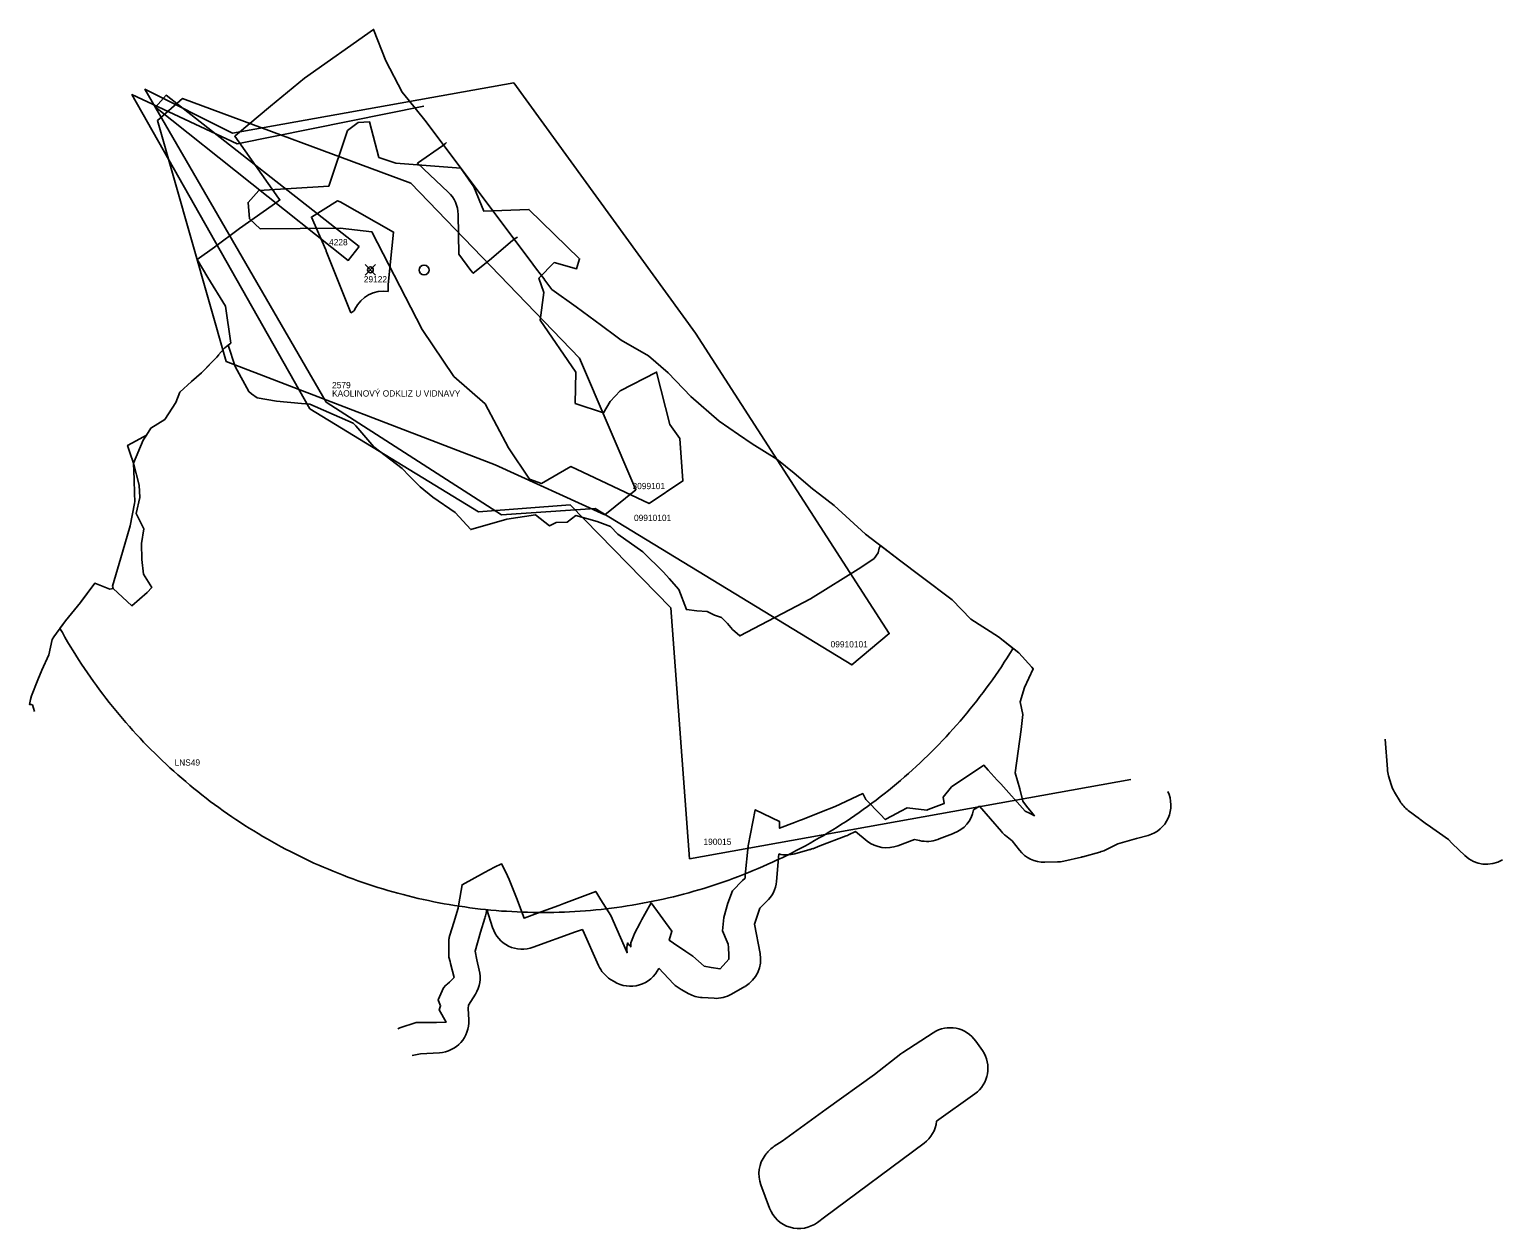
# Model space of a CAD drawing. Extents: x -546762 to -536351, y -1046851 to -1035695.
# Drawn here: x -543675 to -541320, y -1037611 to -1035695 of the extents above; entities that cross this region are included whole.
import ezdxf

# ---------------------------------------------------------------- set-up
doc = ezdxf.new("R2010")
doc.units = 0
for name, color, linetype in [('Vrstva 16', 7, 'Continuous'), ('Vrstva 23', 7, 'Continuous'), ('Vrstva 25', 7, 'Continuous'), ('Vrstva 40', 7, 'Continuous'), ('Vrstva 41', 7, 'Continuous'), ('Vrstva 46', 7, 'Continuous'), ('Vrstva 48', 7, 'Continuous'), ('Vrstva 50', 7, 'Continuous'), ('Vrstva 51', 7, 'Continuous'), ('Vrstva 53', 7, 'Continuous')]:
    doc.layers.add(name, color=color, linetype=linetype)

msp = doc.modelspace()

# ---------------------------------------------------------------- linework, layer by layer
at = {"layer": 'Vrstva 16'}
msp.add_circle((-543043.6, -1036078.9), 7.89, dxfattribs=at)
at = {"layer": 'Vrstva 23'}
for points in [[(-543005.1, -1035954.5), (-543054.3, -1035908.2), (-543014.2, -1035880.6)], [(-543200.8, -1036046.9), (-543223.9, -1035994.4), (-543182.2, -1035968.6), (-543177.6, -1035970.1), (-543092.4, -1036018.3), (-543101, -1036101.8)], [(-542902.1, -1036031.7), (-542939, -1036063.2), (-542965.2, -1036084.2), (-542968.8, -1036079.7), (-542988.1, -1036053.7), (-542989.3, -1035990)], [(-543160.9, -1036147.4), (-543200.1, -1036048.7)], [(-543154.3, -1036141.6), (-543155.4, -1036144), (-543155.9, -1036144.3)], [(-541507, -1036828.4), (-541503.7, -1036876.6)], [(-541501.8, -1036887.1), (-541497.7, -1036901.2)], [(-541492.5, -1036913.1), (-541483.5, -1036928.2)], [(-542165.4, -1036941.7), (-542155.8, -1036935.8), (-542120.8, -1036976.3)], [(-541470.5, -1036942.5), (-541452.2, -1036956.1)], [(-541452, -1036956.2), (-541441, -1036964.3)], [(-541440.3, -1036964.8), (-541406, -1036989.2), (-541400.6, -1036994.7)], [(-542422.4, -1037003.6), (-542410.8, -1036999.1), (-542368.7, -1036983)], [(-542365.4, -1036981.6), (-542354.2, -1036976.3), (-542335.1, -1036991.4)], [(-542286.2, -1036998.9), (-542259.8, -1036988.8), (-542251.6, -1036990.7)], [(-542222.5, -1036988.8), (-542220, -1036987.8), (-542220, -1036987.8), (-542198.9, -1036979.8)], [(-542198.8, -1036979.8), (-542196.7, -1036979)], [(-542114.1, -1036982.8), (-542103.6, -1036991.2), (-542092.1, -1037006)], [(-541955, -1037005.8), (-541934.4, -1036995.9), (-541904.9, -1036987.6), (-541886.4, -1036982.4)], [(-542480.5, -1037055.9), (-542476.7, -1037012)], [(-542451, -1037011.7), (-542427, -1037005.1)], [(-542021.1, -1037023.6), (-541992.6, -1037017)], [(-541990.7, -1037016.5), (-541963.4, -1037009)], [(-541399.4, -1036995.9), (-541379.7, -1037014.7)], [(-542051.5, -1037025.3), (-542031.3, -1037024.8)], [(-542506.5, -1037171.1), (-542515.5, -1037124.1), (-542507.2, -1037098.4), (-542496.1, -1037088.1)], [(-542944.6, -1037106.9), (-542943.6, -1037100.8), (-542934.2, -1037129.8)], [(-542955.5, -1037197.6), (-542959.5, -1037181), (-542962.2, -1037167.2), (-542953.6, -1037136.9), (-542946.4, -1037114.5)], [(-542869.3, -1037161.2), (-542801.7, -1037136.3), (-542790.5, -1037132.8), (-542789.7, -1037134), (-542764.9, -1037190.1)], [(-542668.4, -1037194.8), (-542644.8, -1037219.5)], [(-542745.5, -1037212.4), (-542739.9, -1037215.9)], [(-542632.8, -1037228.7), (-542620.4, -1037235.5)], [(-542552.1, -1037236.1), (-542530.7, -1037223.8)], [(-542972.4, -1037277.1), (-542973.4, -1037258.9), (-542972.7, -1037253.5), (-542961.7, -1037236)], [(-542599.3, -1037241.6), (-542580.1, -1037242.7)], [(-542230.1, -1037297.9), (-542278.2, -1037329.4)], [(-542151.2, -1037326.2), (-542161.6, -1037311.2)], [(-543062.6, -1037334.3), (-543049.6, -1037331.6), (-543019.3, -1037329.8)], [(-542281.5, -1037331.7), (-542323.9, -1037364.6), (-542400.7, -1037419.6)], [(-542224.4, -1037439.2), (-542163.2, -1037395.4)], [(-542401.1, -1037419.9), (-542471.3, -1037471.2), (-542483.9, -1037479.2)], [(-542403.5, -1037592.5), (-542244.4, -1037474.3)], [(-542496.9, -1037491.3), (-542498.4, -1037493.2)], [(-542505.3, -1037540.8), (-542491.3, -1037578.1)], [(-542414.7, -1037600.7), (-542403.5, -1037592.5)]]:
    msp.add_lwpolyline(points, dxfattribs=at)
for centre, start, end in [((-543042.6, -1035839.4), 304.612, 314.1186), ((-543039.3, -1035990.9), 1.0505, 46.8049), ((-542869.7, -1036069.8), 119.8128, 130.451), ((-543246.5, -1036067.1), 21.6456, 23.8041), ((-543108.8, -1036162.5), 80.861, 155.297), ((-543051.3, -1036106.9), 174.0987, 187.0822), ((-543132.1, -1036188.3), 118.3457, 125.0851), ((-541453.8, -1036873.2), 183.9564, 196.1601), ((-541899.8, -1036934.3), 285.6468, 26.265), ((-541449.7, -1036887.3), 196.1601, 211.0699), ((-542214.4, -1036932.3), 290.8209, 349.0875), ((-541440.6, -1036902.3), 211.0699, 233.4016), ((-541422.3, -1036915.9), 233.4016, 233.5731), ((-541411.3, -1036924.1), 233.5731, 234.6081), ((-542386.6, -1036936.3), 290.9828, 295.0141), ((-542304.1, -1036952.2), 231.5776, 290.9837), ((-542240.2, -1036942), 256.8934, 290.731), ((-542216.6, -1036933.1), 290.7371, 290.8209), ((-542083, -1036943.6), 220.8366, 231.547), ((-542464.4, -1036963.6), 255.7148, 285.5315), ((-542440.4, -1036956.9), 285.5315, 291.0013), ((-542052.6, -1036975.3), 217.8283, 271.2509), ((-542003.9, -1036968.3), 283.0342, 285.367), ((-541976.6, -1036960.8), 285.367, 295.6775), ((-541364.8, -1036959.8), 224.2993, 226.2334), ((-541345.2, -1036978.6), 226.2334, 300.6936), ((-542032.4, -1036974.9), 271.2509, 283.0342), ((-542530.3, -1037051.6), 313.1264, 355.0378), ((-542994, -1037099.2), 342.1292, 351.1556), ((-542886.7, -1037114.3), 198.0248, 290.2592), ((-542555.6, -1037180.4), 299.9655, 10.7848), ((-543004, -1037209.4), 327.8671, 13.6912), ((-542719.2, -1037169.9), 203.8157, 238.1981), ((-542713.6, -1037173.4), 238.1981, 334.6326), ((-542608.7, -1037184.9), 223.7994, 241.1857), ((-542596.3, -1037191.7), 241.1857, 266.567), ((-542577.1, -1037192.8), 266.567, 299.9655), ((-543022.3, -1037279.9), 273.4472, 3.228), ((-542202.7, -1037339.7), 34.7785, 123.1792), ((-542250.8, -1037371.2), 123.1792, 127.8022), ((-542192.3, -1037354.7), 305.5673, 34.7785), ((-542371.6, -1037460.2), 125.5844, 126.164), ((-542274.2, -1037434.2), 306.5953, 354.2175), ((-542456.9, -1037521.3), 122.6017, 143.0357), ((-542458.4, -1037523.3), 143.0357, 200.4685), ((-542444.5, -1037560.6), 200.4685, 306.573), ((-542433.3, -1037552.3), 306.573, 306.5953)]:
    msp.add_arc(centre, 50, start, end, dxfattribs=at)
at = {"layer": 'Vrstva 25'}
msp.add_lwpolyline([(-543085.7, -1037291.6), (-543082.6, -1037289.8), (-543056.1, -1037281.6), (-543040.8, -1037281.4), (-543023.7, -1037281.2), (-543008.4, -1037281), (-543019.5, -1037261.3), (-543017.2, -1037254.8), (-543020.5, -1037246.5), (-543021.1, -1037245.2), (-543012.8, -1037225.9), (-543008.7, -1037221.9), (-543008, -1037221.3), (-543006.9, -1037220.2), (-543003.3, -1037216.8), (-542998.8, -1037212.5), (-542995.6, -1037209.5), (-543001.3, -1037187.3), (-543002.1, -1037184.1), (-543003.9, -1037176.9), (-543004, -1037159.9), (-543004, -1037158), (-543004, -1037148.2), (-543003.8, -1037147.2), (-543003.5, -1037145.4), (-543002.4, -1037141.9), (-542996.2, -1037121.7), (-542989.1, -1037098.5), (-542988, -1037091.9), (-542982.9, -1037061.3), (-542946.9, -1037041.7), (-542931.3, -1037033.2), (-542919.7, -1037027.9), (-542913, -1037040.9), (-542907.9, -1037053.1), (-542895.8, -1037082.1), (-542883.9, -1037114.9), (-542862.3, -1037106.9), (-542828.4, -1037094.3), (-542820.5, -1037091.3), (-542769.2, -1037071.9), (-542761, -1037085.5), (-542745.4, -1037110.5), (-542720.3, -1037167.3), (-542719.2, -1037169.9), (-542719.4, -1037165.5), (-542719.7, -1037161.6), (-542718.6, -1037154.2), (-542715.3, -1037158.1), (-542713.3, -1037160.5), (-542713.1, -1037154.2), (-542713.1, -1037154.2), (-542708.9, -1037143.3), (-542707.2, -1037139), (-542698.5, -1037122.2), (-542695.6, -1037116.7), (-542691, -1037108), (-542680.9, -1037090.2), (-542647.4, -1037135.5), (-542652, -1037149.8), (-542645.1, -1037154.4), (-542625.3, -1037167.8), (-542614.1, -1037175.4), (-542596.2, -1037191.2), (-542584.5, -1037193.3), (-542570.5, -1037195.8), (-542556.3, -1037180.3), (-542556.6, -1037175.2), (-542556.7, -1037172.2), (-542557.2, -1037163), (-542557.2, -1037161.7), (-542557.5, -1037156), (-542559.1, -1037152.3), (-542566.8, -1037135), (-542564.6, -1037113.6), (-542557.9, -1037090.6), (-542550.8, -1037070.8), (-542534.5, -1037054.5), (-542530.6, -1037050.6), (-542530.2, -1037046.1), (-542525.7, -1036998.8), (-542514.4, -1036941.4), (-542475.4, -1036960.3), (-542475.3, -1036960.4), (-542475.5, -1036971), (-542451.7, -1036961.8), (-542443.7, -1036958.8), (-542438.8, -1036956.8), (-542408.2, -1036944.8), (-542386.6, -1036936.3), (-542342.3, -1036915.6), (-542337.3, -1036925.1), (-542314.2, -1036949.1), (-542306.4, -1036957.2), (-542295.2, -1036951.2), (-542281.5, -1036943.8), (-542271.6, -1036938.4), (-542240.2, -1036942), (-542237.7, -1036941.1), (-542216.6, -1036933.1), (-542212.5, -1036931.5), (-542214.1, -1036921.3), (-542200.5, -1036904.7), (-542148.6, -1036870.2), (-542141.7, -1036877.9), (-542127.3, -1036894), (-542121.9, -1036900.1), (-542083, -1036943.6), (-542075.7, -1036946.8), (-542072.5, -1036948.6), (-542069.1, -1036950.6), (-542068.1, -1036951.1), (-542070.5, -1036948.1), (-542080.4, -1036935.6), (-542086.7, -1036927.6), (-542091.1, -1036907.9), (-542098.6, -1036882.2), (-542089.2, -1036813.1), (-542086.7, -1036789.2), (-542090.6, -1036768.7), (-542084.1, -1036745.9), (-542069.8, -1036716.4), (-542072.1, -1036713.8), (-542092.8, -1036690.7), (-542125.6, -1036665.3), (-542169.9, -1036636.7), (-542199.3, -1036606), (-542248.8, -1036568.9), (-542283.5, -1036542.7), (-542314, -1036519.2), (-542316.1, -1036523.3), (-542317.9, -1036531.1), (-542324.2, -1036540), (-542345.7, -1036554.4), (-542426.2, -1036604.1), (-542538.7, -1036663.7), (-542550.6, -1036653.3), (-542558.7, -1036643.7), (-542568, -1036634.4), (-542579.4, -1036630.4), (-542591.3, -1036624.8), (-542607.6, -1036623.3), (-542624.4, -1036621.6), (-542636.6, -1036589.7), (-542652.1, -1036571.8), (-542660.8, -1036561.8), (-542693.8, -1036529), (-542734.2, -1036500.8), (-542745.5, -1036488.6), (-542767.1, -1036480.6), (-542801.1, -1036471.2), (-542815.1, -1036482), (-542832.6, -1036482.3), (-542843.1, -1036487.6), (-542865.6, -1036470.3), (-542911.4, -1036477.1), (-542969.2, -1036493.7), (-542994, -1036466.4), (-543029.9, -1036441.8), (-543050, -1036425.5), (-543061.5, -1036413.8), (-543067.5, -1036407.6), (-543079, -1036395.9), (-543124.2, -1036361.7), (-543152.7, -1036328), (-543157.3, -1036323.6), (-543226.5, -1036293.2), (-543239.7, -1036292.1), (-543279.8, -1036288.3), (-543310.7, -1036283.2), (-543319.4, -1036276.6), (-543323.6, -1036273.2), (-543345.5, -1036233.3), (-543356.8, -1036199), (-543359.4, -1036201.1), (-543362.4, -1036203.4), (-543363.8, -1036205), (-543372.1, -1036214.7), (-543372.5, -1036215.2), (-543374.9, -1036218.2), (-543375.3, -1036218.6), (-543383.5, -1036226.9), (-543389.5, -1036233), (-543399.7, -1036243.4), (-543415.6, -1036257.2), (-543434.2, -1036274.3), (-543440.4, -1036290.8), (-543458.3, -1036318), (-543480.5, -1036331.6), (-543487.3, -1036342.7), (-543504.2, -1036351.9), (-543517.8, -1036359.3), (-543513.9, -1036370.7), (-543508.1, -1036387.7), (-543507.2, -1036413.8), (-543506.4, -1036435.9), (-543506, -1036448.8), (-543506.7, -1036452.1), (-543513.6, -1036487.5), (-543525.9, -1036529.6), (-543541.8, -1036584.1), (-543540.8, -1036587.9), (-543546.1, -1036588.7), (-543570, -1036579.1), (-543590.7, -1036607.1), (-543592.9, -1036610.1), (-543617, -1036639.6), (-543635.6, -1036665.3), (-543638.4, -1036669.3), (-543643.6, -1036693.8), (-543654.6, -1036718.2), (-543661.4, -1036733.6), (-543671.5, -1036759.2), (-543673.1, -1036765.1), (-543674.6, -1036773.2), (-543671.6, -1036773.2), (-543669.8, -1036773.8), (-543666.6, -1036784.2)], dxfattribs=at)
at = {"layer": 'Vrstva 40'}
msp.add_lwpolyline([(-542900, -1035780), (-543350, -1035860), (-543490, -1035790), (-543200, -1036290), (-542920, -1036470), (-542770, -1036460), (-542360, -1036710), (-542300, -1036660), (-542610, -1036180), (-542900, -1035780)], dxfattribs=at)
at = {"layer": 'Vrstva 41'}
msp.add_lwpolyline([(-542964, -1035946), (-542985, -1035916), (-543089, -1035908), (-543116, -1035899), (-543131, -1035842), (-543149, -1035843), (-543166, -1035856), (-543196, -1035945), (-543308, -1035952), (-543325, -1035971), (-543323, -1035997), (-543306, -1036013), (-543178, -1036012), (-543127, -1036018), (-543047, -1036174), (-542996, -1036249), (-542946, -1036293), (-542909, -1036363), (-542875, -1036413), (-542856, -1036420), (-542809, -1036393), (-542684, -1036452), (-542630, -1036416), (-542635, -1036348), (-542651, -1036326), (-542672, -1036242), (-542730, -1036272), (-542746, -1036289), (-542757, -1036307), (-542802, -1036292), (-542801, -1036242), (-542858, -1036159), (-542852, -1036115), (-542860, -1036092), (-542836, -1036067), (-542800, -1036077), (-542795, -1036061), (-542876, -1035982), (-542948, -1035985), (-542964, -1035946)], dxfattribs=at)
at = {"layer": 'Vrstva 46'}
msp.add_lwpolyline([(-543044.2, -1035817.1), (-543342.3, -1035877.2), (-543510.9, -1035798.6), (-543226.2, -1036300.5), (-542956.5, -1036465.3), (-542810.4, -1036454.1), (-542649.3, -1036618.9), (-542619.3, -1037019.7), (-541913.6, -1036892.8)], dxfattribs=at)
at = {"layer": 'Vrstva 48'}
msp.add_lwpolyline([(-543625.8, -1036651.7), (-543622, -1036658.4), (-543617.9, -1036665.7), (-543613.6, -1036672.9), (-543609.3, -1036680.1), (-543604.9, -1036687.3), (-543600.5, -1036694.4), (-543596, -1036701.5), (-543591.4, -1036708.5), (-543586.7, -1036715.5), (-543582, -1036722.5), (-543577.2, -1036729.4), (-543572.4, -1036736.2), (-543567.4, -1036743.1), (-543562.5, -1036749.8), (-543557.4, -1036756.5), (-543552.3, -1036763.2), (-543547.1, -1036769.8), (-543541.9, -1036776.4), (-543536.6, -1036782.9), (-543531.3, -1036789.4), (-543525.8, -1036795.8), (-543520.4, -1036802.2), (-543514.8, -1036808.5), (-543509.2, -1036814.7), (-543503.6, -1036821), (-543497.8, -1036827.1), (-543492.1, -1036833.2), (-543486.2, -1036839.3), (-543480.3, -1036845.2), (-543474.4, -1036851.2), (-543468.4, -1036857), (-543462.3, -1036862.9), (-543456.2, -1036868.6), (-543450, -1036874.3), (-543443.8, -1036880), (-543437.5, -1036885.5), (-543431.2, -1036891.1), (-543424.8, -1036896.5), (-543418.4, -1036901.9), (-543411.9, -1036907.3), (-543405.4, -1036912.5), (-543398.8, -1036917.7), (-543392.1, -1036922.9), (-543385.5, -1036928), (-543378.7, -1036933), (-543371.9, -1036938), (-543365.1, -1036942.9), (-543358.2, -1036947.7), (-543351.3, -1036952.5), (-543344.4, -1036957.2), (-543337.4, -1036961.8), (-543330.3, -1036966.3), (-543323.2, -1036970.8), (-543316.1, -1036975.3), (-543308.9, -1036979.6), (-543301.7, -1036983.9), (-543294.4, -1036988.1), (-543287.1, -1036992.3), (-543279.8, -1036996.4), (-543272.4, -1037000.4), (-543265, -1037004.3), (-543257.5, -1037008.2), (-543250, -1037012), (-543242.5, -1037015.7), (-543234.9, -1037019.4), (-543227.3, -1037023), (-543219.7, -1037026.5), (-543212, -1037029.9), (-543204.3, -1037033.3), (-543196.6, -1037036.6), (-543188.9, -1037039.8), (-543181.1, -1037043), (-543173.3, -1037046), (-543165.4, -1037049), (-543157.5, -1037052), (-543149.6, -1037054.8), (-543141.7, -1037057.6), (-543133.7, -1037060.3), (-543125.8, -1037062.9), (-543117.8, -1037065.4), (-543109.7, -1037067.9), (-543101.7, -1037070.3), (-543093.6, -1037072.6), (-543085.5, -1037074.8), (-543077.4, -1037077), (-543069.2, -1037079.1), (-543061.1, -1037081.1), (-543052.9, -1037083), (-543044.7, -1037084.9), (-543036.5, -1037086.6), (-543028.3, -1037088.3), (-543020, -1037089.9), (-543011.8, -1037091.5), (-543003.5, -1037092.9), (-542995.2, -1037094.3), (-542986.9, -1037095.6), (-542978.6, -1037096.8), (-542970.3, -1037098), (-542962, -1037099), (-542953.6, -1037100), (-542945.3, -1037100.9), (-542936.9, -1037101.7), (-542928.5, -1037102.5), (-542920.2, -1037103.2), (-542911.8, -1037103.7), (-542903.4, -1037104.2), (-542895, -1037104.7), (-542886.6, -1037105), (-542878.2, -1037105.3), (-542869.8, -1037105.5), (-542861.4, -1037105.6), (-542853, -1037105.6), (-542844.6, -1037105.5), (-542836.2, -1037105.4), (-542827.8, -1037105.2), (-542819.4, -1037104.9), (-542811, -1037104.5), (-542802.6, -1037104.1), (-542794.3, -1037103.5), (-542785.9, -1037102.9), (-542777.5, -1037102.2), (-542769.2, -1037101.4), (-542760.8, -1037100.6), (-542752.4, -1037099.7), (-542744.1, -1037098.6), (-542735.8, -1037097.5), (-542727.5, -1037096.4), (-542719.2, -1037095.1), (-542710.9, -1037093.8), (-542702.6, -1037092.4), (-542694.3, -1037090.9), (-542686.1, -1037089.3), (-542677.8, -1037087.7), (-542669.6, -1037086), (-542661.4, -1037084.2), (-542653.2, -1037082.3), (-542645, -1037080.3), (-542636.9, -1037078.3), (-542628.8, -1037076.2), (-542620.7, -1037074), (-542612.6, -1037071.7), (-542604.5, -1037069.4), (-542596.5, -1037067), (-542588.4, -1037064.5), (-542580.4, -1037061.9), (-542572.5, -1037059.2), (-542564.5, -1037056.5), (-542556.6, -1037053.7), (-542548.7, -1037050.8), (-542540.8, -1037047.9), (-542533, -1037044.9), (-542525.2, -1037041.8), (-542517.4, -1037038.6), (-542509.7, -1037035.3), (-542502, -1037032), (-542494.3, -1037028.6), (-542486.6, -1037025.2), (-542479, -1037021.6), (-542471.4, -1037018), (-542463.9, -1037014.3), (-542456.4, -1037010.6), (-542448.9, -1037006.7), (-542441.4, -1037002.8), (-542434, -1036998.9), (-542426.7, -1036994.8), (-542419.4, -1036990.7), (-542412.1, -1036986.5), (-542404.8, -1036982.3), (-542397.6, -1036978), (-542390.5, -1036973.6), (-542383.3, -1036969.1), (-542376.3, -1036964.6), (-542369.2, -1036960), (-542362.2, -1036955.3), (-542355.3, -1036950.6), (-542348.4, -1036945.8), (-542341.5, -1036941), (-542334.7, -1036936.1), (-542328, -1036931.1), (-542321.2, -1036926), (-542314.6, -1036920.9), (-542308, -1036915.7), (-542301.4, -1036910.5), (-542294.9, -1036905.2), (-542288.4, -1036899.8), (-542282, -1036894.4), (-542275.6, -1036888.9), (-542269.3, -1036883.4), (-542263.1, -1036877.8), (-542256.9, -1036872.1), (-542250.7, -1036866.4), (-542244.6, -1036860.6), (-542238.6, -1036854.8), (-542232.6, -1036848.9), (-542226.7, -1036842.9), (-542220.8, -1036836.9), (-542215, -1036830.9), (-542209.2, -1036824.7), (-542203.5, -1036818.6), (-542197.9, -1036812.3), (-542192.3, -1036806.1), (-542186.8, -1036799.7), (-542181.3, -1036793.3), (-542175.9, -1036786.9), (-542170.6, -1036780.4), (-542165.3, -1036773.9), (-542160.1, -1036767.3), (-542155, -1036760.6), (-542149.9, -1036754), (-542144.9, -1036747.2), (-542139.9, -1036740.4), (-542135, -1036733.6), (-542130.2, -1036726.7), (-542125.5, -1036719.8), (-542120.8, -1036712.8), (-542116.1, -1036705.8), (-542111.6, -1036698.8), (-542107.1, -1036691.7), (-542102.7, -1036684.5), (-542102.1, -1036683.5), (-542125.6, -1036665.3), (-542169.9, -1036636.7), (-542199.3, -1036606), (-542248.8, -1036568.9), (-542283.5, -1036542.7), (-542337.9, -1036500.9), (-542388.3, -1036455), (-542411.4, -1036437.3), (-542422.8, -1036428.7), (-542452, -1036403.6), (-542480, -1036381.3), (-542519, -1036356.5), (-542540.9, -1036341.6), (-542571.9, -1036320.4), (-542617, -1036281.3), (-542653.7, -1036243.4), (-542685.1, -1036216.3), (-542728.5, -1036190.8), (-542737.3, -1036184.4), (-542760.1, -1036167.7), (-542800.8, -1036138), (-542839.6, -1036109.9), (-542850.5, -1036095.4), (-542852.5, -1036092.7), (-542864, -1036077.3), (-542869.7, -1036069.8), (-542936.7, -1035980.7), (-543042.6, -1035839.4), (-543069.2, -1035806.4), (-543078.5, -1035794.9), (-543104.7, -1035744.6), (-543124.3, -1035694.5), (-543234.9, -1035772.4), (-543289.2, -1035817), (-543341.9, -1035861.5), (-543346.5, -1035865.2), (-543276.4, -1035963.9), (-543274.2, -1035967), (-543279.3, -1035970.3), (-543286.8, -1035975.7), (-543338.8, -1036012.6), (-543378.7, -1036042.3), (-543406.7, -1036061.9), (-543389.2, -1036090.9), (-543361.3, -1036136.8), (-543352.7, -1036195.7), (-543356.8, -1036199), (-543359.4, -1036201.1), (-543362.4, -1036203.4), (-543363.8, -1036205), (-543372.1, -1036214.7), (-543372.5, -1036215.2), (-543374.9, -1036218.2), (-543375.3, -1036218.6), (-543383.5, -1036226.9), (-543399.7, -1036243.4), (-543415.6, -1036257.2), (-543434.2, -1036274.3), (-543440.4, -1036290.8), (-543458.3, -1036318), (-543480.5, -1036331.6), (-543487.3, -1036342.7), (-543492.9, -1036350.6), (-543508.1, -1036387.7), (-543499, -1036422.7), (-543498.1, -1036442.3), (-543503.8, -1036468), (-543491.9, -1036492.5), (-543495.7, -1036516.1), (-543494.8, -1036541.3), (-543492.5, -1036564.8), (-543479.1, -1036586.3), (-543486.5, -1036594), (-543510.9, -1036615.5), (-543540.8, -1036587.9), (-543546.1, -1036588.7), (-543570, -1036579.1), (-543592.9, -1036610.1), (-543617, -1036639.6), (-543625.8, -1036651.7)], dxfattribs=at)
at = {"layer": 'Vrstva 50'}
msp.add_lwpolyline([(-543065, -1035940), (-543430, -1035805), (-543470, -1035840), (-543360, -1036225), (-542930, -1036390), (-542755, -1036470), (-542705, -1036430), (-542795, -1036220), (-543065, -1035940)], dxfattribs=at)
at = {"layer": 'Vrstva 51'}
for p, q in [((-543137.8, -1036086.9), (-543121.2, -1036070.3)), ((-543137.8, -1036070.3), (-543121.2, -1036086.9))]:
    msp.add_line(p, q, dxfattribs=at)
msp.add_circle((-543129.5, -1036078.6), 4.61, dxfattribs=at)
at = {"layer": 'Vrstva 53'}
msp.add_lwpolyline([(-543147.3, -1036041.6), (-543165, -1036063.5), (-543472.9, -1035818.9), (-543456, -1035799.7)], close=True, dxfattribs=at)

# ---------------------------------------------------------------- texts
at = {"layer": 'Vrstva 40'}
for p in [(-542708.1, -1036480), (-542393.8, -1036682)]:
    msp.add_text('09910101', height=10, dxfattribs=at).set_placement(p)
at = {"layer": 'Vrstva 41'}
msp.add_text('3099101', height=10, dxfattribs=at).set_placement((-542710.5, -1036429.1))
at = {"layer": 'Vrstva 46'}
msp.add_text('190015', height=10, dxfattribs=at).set_placement((-542597.1, -1036997.5))
at = {"layer": 'Vrstva 48'}
msp.add_text('LNS49', height=10, dxfattribs=at).set_placement((-543442.7, -1036870.9))
at = {"layer": 'Vrstva 50'}
for s, p in [('2579', (-543190.8, -1036267.9)), ('KAOLINOVÝ ODKLIZ U VIDNAVY', (-543190.8, -1036281.1))]:
    msp.add_text(s, height=10, dxfattribs=at).set_placement(p)
at = {"layer": 'Vrstva 51'}
msp.add_text('29122', height=10, dxfattribs=at).set_placement((-543140.1, -1036098.7))
at = {"layer": 'Vrstva 53'}
msp.add_text('4228', height=10, dxfattribs=at).set_placement((-543195.6, -1036039.4))

doc.saveas('drawing.dxf')
